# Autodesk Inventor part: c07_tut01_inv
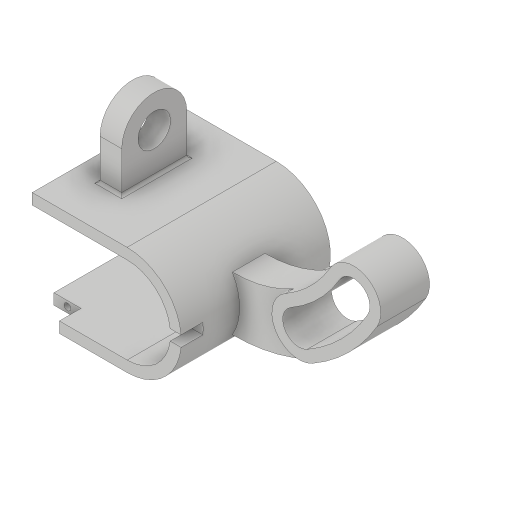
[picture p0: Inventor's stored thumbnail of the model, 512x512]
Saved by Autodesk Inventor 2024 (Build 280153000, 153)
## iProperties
Created: 2017-04
Part Number: c07_tut01_inv
Material: Generic
Document SubType Name: Modeling
Designer: CADCIM 00
Density: 1 g/cm^3
Appearance: Default
Author: CADCIM 00
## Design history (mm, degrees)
sketch "Sketch1"
  geometry: L1 (0, 16)-(35, 16); L2 (35, 16)-(35, 20); L3 (35, 20)-(0, 20); L4 (0, -20)-(35, -20); L5 (35, -20)-(35, -16); L6 (35, -16)-(0, -16); A1 r 16 centre (0, 0) between (0, 16) and (0, -16); A2 r 20 centre (0, 0) between (0, 20) and (0, -20); 1 further point
  constraints: 12 end point, 4 point on circle, 4 tangent, 3 perpendicular, 2 centre point, 2 point on line, 1 coincident, 1 concentric, 1 horizontal, 1 parallel
  dimensions: "d1" = 20 radius of A2; "d3" = 35 distance from line of point (0, 0) L5; "d37" = 16 radius of A1
extrude "Extrusion1" new body sketch "Sketch1" stored distance "d4" = 55; taper "d5" = 0 deg
sketch "Sketch2"
  geometry: A1 r 45 centre (-17.5, 55) between (-56.409, 32.393) and (-17.32, 10); A2 r 65 centre (-17.5, 55) between (-73.702, 22.345) and (-17.321, -10); A3 r 10 centre (-65.055, 27.369) between (-56.409, 32.393) and (-73.702, 22.345); A4 r 20 centre (0, 0) between (0, 20) and (0, -20) reference; A5 r 20 centre (0, 0) between (-17.32, 10) and (-17.321, -10); 1 further point
  constraints: 10 point on circle, 4 centre point, 2 tangent, 1 coincident
  dimensions: "d6" = 45 radius of A1; "d7" = 65 radius of A2; "d8" = 17.5 horizontal distance of point (0, 0) A1.centre; "d9" = 55 vertical distance of point (0, 0) A1.centre; "d10" = 60 deg dimension on A1.centre A3.centre A2.end
extrude "Extrusion2" join sketch "Sketch2" stored distance "d11" = 12; taper "d12" = 0 deg
sketch "Sketch3"
  geometry: A1 r 55 centre (-17.5, 55) between (-65.055, 27.369) and (-44.868, 7.293); A2 r 65 centre (-17.5, 55) between (-73.702, 22.345) and (-49.845, -1.381); A3 r 45 centre (-17.5, 55) between (-56.409, 32.393) and (-39.892, 15.967); A4 r 10 centre (-65.055, 27.369) between (-56.409, 32.393) and (-73.702, 22.345); A5 r 10 centre (-44.868, 7.293) between (-49.845, -1.381) and (-39.892, 15.967); A6 r 45 centre (-17.5, 55) between (-56.409, 32.393) and (-17.32, 10) reference; A7 r 65 centre (-17.5, 55) between (-73.702, 22.345) and (-17.321, -10) reference; A8 r 10 centre (-65.055, 27.369) between (-56.409, 32.393) and (-73.702, 22.345) reference; 1 further point
  constraints: 10 point on circle, 7 tangent, 5 centre point, 1 concentric
  dimensions: "d13" = 30 deg dimension on A1.centre A1.end A1.start
extrude "Extrusion3" join sketch "Sketch3" stored distance "d14" = 18; taper "d15" = 0 deg
sketch "Sketch4"
  geometry: A1 r 55 centre (17.5, 55) between (44.868, 7.293) and (65.055, 27.369); A2 r 61 centre (17.5, 55) between (47.854, 2.088) and (70.243, 24.354); A3 r 49 centre (17.5, 55) between (41.883, 12.497) and (59.867, 30.383); A4 r 6 centre (44.868, 7.293) between (41.883, 12.497) and (47.854, 2.088); A5 r 6 centre (65.055, 27.369) between (70.243, 24.354) and (59.867, 30.383); A6 r 45 centre (17.5, 55) between (39.892, 15.967) and (56.409, 32.393) reference; A7 r 10 centre (65.055, 27.369) between (73.702, 22.345) and (56.409, 32.393) reference; A8 r 10 centre (44.868, 7.293) between (39.892, 15.967) and (49.845, -1.381) reference; 1 further point
  constraints: 10 point on circle, 5 centre point, 4 tangent, 3 concentric
  dimensions: "d16" = 6 radius of A5
extrude "Extrusion4" cut sketch "Sketch4" extent not by distance; stored distance "d17" = 18; taper "d18" = 0 deg
workplane "Work Plane1"
sketch "Sketch5"
  geometry: L1 (0, 39.5)-(15, 39.5); L2 (15, 15.5)-(0, 15.5); L3 (0, 55)-(0, 0) reference; L4 (0, 39.5)-(0, 15.5); L5 (-40, 0)-(0, 0) reference; C1 r 6 at (15, 27.5); A1 r 12 centre (15, 27.5) between (15, 15.5) and (15, 39.5); 1 further point
  constraints: 6 end point, 2 centre point, 2 point on circle, 2 point on line, 2 tangent, 1 coincident, 1 collinear, 1 horizontal, 1 parallel
  dimensions: "d20" = 12 radius of A1; "d21" = 12 diameter of C1; "d22" = 15 distance from line of L3 A1.centre; "d23" = 27.5 distance from line of L5 A1.centre
extrude "Extrusion5" join sketch "Sketch5" distance "d24" = 8; taper "d25" = 0 deg
fillet "Fillet1" dims "d26" = 1
sketch "Sketch6"
  geometry: L1 (-35, -16)-(-35, -20) reference; L2 (-35, -20)-(0, -20) reference; L3 (-35, -16)-(-25, -16); L4 (-25, -16)-(-25, -20); L5 (-25, -20)-(-35, -20); L6 (-35, -20)-(-35, -16); L7 (15.631, 2)-(21.208, 2); L8 (21.208, 2)-(21.208, -2); L9 (21.208, -2)-(15.631, -2); L10 (15.631, -2)-(15.631, 2); A1 r 20 centre (0, 0) between (0, -20) and (0, 20) reference; 1 further point
  constraints: 16 end point, 4 parallel, 2 horizontal, 1 perpendicular, 1 point on line
  dimensions: "d27" = 10 distance of L1.start L3.end; "d28" = 4 distance of L9.end L7.start; "d29" = 2 distance from line of L7 point (0, 0)
extrude "Extrusion6" cut sketch "Sketch6" distance "d30" = 8; taper "d31" = 0 deg
sketch "Sketch7"
  geometry: L1 (-35, -20)-(-35, -16) reference; L2 (-25, -20)-(-35, -20) reference; C1 r 1.25 at (-30, -18); 1 further point
  constraints: 1 centre point
  dimensions: "d32" = 5 distance from line of L1 C1.centre; "d33" = 2 distance from line of L2 C1.centre; "d34" = 2.5 diameter of C1
extrude "Extrusion7" cut sketch "Sketch7" distance "d35" = 4; taper "d36" = 0 deg
body "Solid1"
other parameters: "d19" = -17.5
